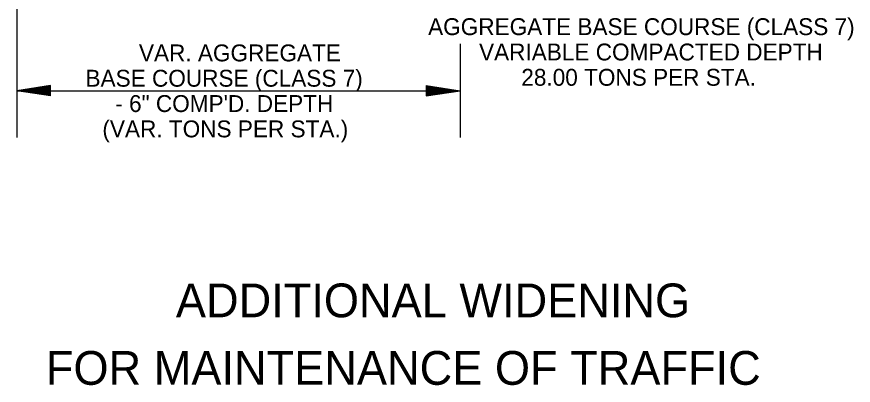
# Model space of a CAD drawing. Extents: x 836 to 5683, y -463 to 1545.
# Drawn here: x 4471.6 to 4768.9, y -462.6 to -331.6 of the extents above; entities that cross this region are included whole.
import ezdxf

# ---------------------------------------------------------------- set-up
doc = ezdxf.new("R2010")
doc.units = 0
doc.layers.add('Default', color=7, linetype='Continuous')
doc.layers.add('R_Border', color=7, linetype='Continuous')

msp = doc.modelspace()

# ---------------------------------------------------------------- linework, layer by layer
at = {"layer": 'Default'}
for p, q in [((4471.56, -301.99), (4471.56, -374.56)), ((4629.11, -341.2), (4629.11, -374.56)), ((4483.56, -356.08), (4471.56, -357.88)), ((4483.56, -356.38), (4473.56, -357.88)), ((4483.56, -356.69), (4475.63, -357.88)), ((4483.56, -359.68), (4483.56, -356.08)), ((4617.11, -356.08), (4629.11, -357.88)), ((4617.11, -356.08), (4617.11, -359.68)), ((4617.11, -356.38), (4627.11, -357.88)), ((4617.11, -356.69), (4625.04, -357.88)), ((4471.56, -357.88), (4629.11, -357.88)), ((4483.56, -359.68), (4471.56, -357.88)), ((4483.56, -359.38), (4473.56, -357.88)), ((4483.56, -359.07), (4475.63, -357.88)), ((4483.56, -356.99), (4477.63, -357.88)), ((4483.56, -358.77), (4477.63, -357.88)), ((4483.56, -357.29), (4479.66, -357.88)), ((4483.56, -358.46), (4479.66, -357.88)), ((4483.56, -357.6), (4481.66, -357.88)), ((4483.56, -358.16), (4481.66, -357.88)), ((4617.11, -356.99), (4623.04, -357.88)), ((4617.11, -357.3), (4621.01, -357.88)), ((4617.11, -357.6), (4619.01, -357.88)), ((4617.11, -359.68), (4629.11, -357.88)), ((4617.11, -358.47), (4621.01, -357.88)), ((4617.11, -359.07), (4625.04, -357.88)), ((4617.11, -359.38), (4627.11, -357.88)), ((4617.11, -358.77), (4623.04, -357.88)), ((4617.11, -358.16), (4619.01, -357.88))]:
    msp.add_line(p, q, dxfattribs=at)

# ---------------------------------------------------------------- texts
for s, p in [('AGGREGATE BASE COURSE (CLASS 7)', (4617.76, -338.12)), ('VAR. AGGREGATE', (4514.99, -347.45)), ('VARIABLE COMPACTED DEPTH', (4635.86, -347.12)), ('BASE COURSE (CLASS 7)', (4496, -356.45)), ('28.00 TONS PER STA.', (4650.88, -356.12)), ('- 6" COMP\'D. DEPTH', (4506.58, -365.45)), ('(VAR. TONS PER STA.)', (4502, -374.45))]:
    msp.add_text(s, height=6, dxfattribs=at).set_placement(p)
at = {"layer": 'R_Border'}
for s, p in [('ADDITIONAL WIDENING ', (4528.12, -438.4)), ('FOR MAINTENANCE OF TRAFFIC', (4481.92, -462.4))]:
    msp.add_text(s, height=12, dxfattribs=at).set_placement(p)

doc.saveas('drawing.dxf')
